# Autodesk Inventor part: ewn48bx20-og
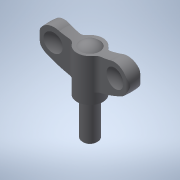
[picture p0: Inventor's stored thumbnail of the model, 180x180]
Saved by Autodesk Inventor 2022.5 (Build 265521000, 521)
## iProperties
Created: 2017-05
Part Number: ewn48bx20-og
Material: 一般
Document SubType Name: Modeling
Designer: imaocorp
Density: 1 g/cm^3
Appearance: 既定
Author: imaocorp
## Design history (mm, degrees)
node "ewn48bx20-og.x_t1"
node "ewn48bx20-og"
node "Base1"
